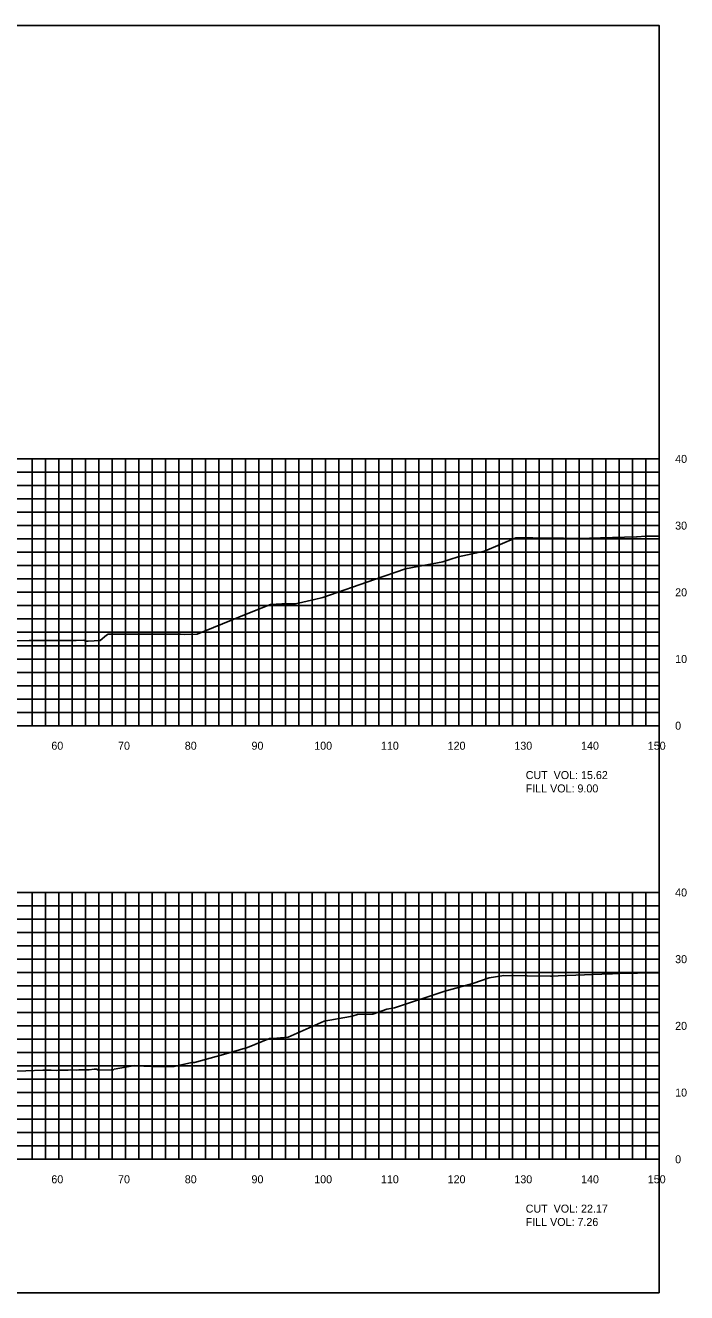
# Model space of a CAD drawing. Extents: x 1797645 to 1803805, y 248417 to 250269.
# Drawn here: x 1802686 to 1802785.1, y 250079.4 to 250269.4 of the extents above; entities that cross this region are included whole.
import ezdxf

# ---------------------------------------------------------------- set-up
doc = ezdxf.new("R2010")
doc.units = 0
for name, color, linetype in [('10', 7, 'Continuous'), ('31', 7, 'Continuous'), ('60', 7, 'Continuous'), ('ANNO-TXT', 7, 'Continuous'), ('Level 62', 7, 'Continuous'), ('M-ROADS', 7, 'Continuous')]:
    doc.layers.add(name, color=color, linetype=linetype)

msp = doc.modelspace()

# ---------------------------------------------------------------- linework, layer by layer
msp.add_lwpolyline([(1802481, 250079.43), (1802781, 250079.43), (1802781, 250269.43), (1802481, 250269.43)], close=True)
at = {"layer": '60'}
for p, q in [((1802781, 250164.43), (1802781, 250204.43)), ((1802781.06, 250204.43), (1802781, 250204.43)), ((1802781.06, 250194.43), (1802781, 250194.43)), ((1802781.06, 250184.43), (1802781, 250184.43)), ((1802781.06, 250174.43), (1802781, 250174.43)), ((1802481, 250164.43), (1802781, 250164.43)), ((1802691, 250164.37), (1802691, 250164.43)), ((1802701, 250164.37), (1802701, 250164.43)), ((1802711, 250164.37), (1802711, 250164.43)), ((1802721, 250164.37), (1802721, 250164.43)), ((1802731, 250164.37), (1802731, 250164.43)), ((1802741, 250164.37), (1802741, 250164.43)), ((1802751, 250164.37), (1802751, 250164.43)), ((1802761, 250164.37), (1802761, 250164.43)), ((1802771, 250164.37), (1802771, 250164.43)), ((1802781, 250164.37), (1802781, 250164.43)), ((1802781.06, 250164.43), (1802781, 250164.43)), ((1802781, 250099.43), (1802781, 250139.43)), ((1802781.06, 250139.43), (1802781, 250139.43)), ((1802781.06, 250129.43), (1802781, 250129.43)), ((1802781.06, 250119.43), (1802781, 250119.43)), ((1802781.06, 250109.43), (1802781, 250109.43)), ((1802481, 250099.43), (1802781, 250099.43)), ((1802691, 250099.37), (1802691, 250099.43)), ((1802701, 250099.37), (1802701, 250099.43)), ((1802711, 250099.37), (1802711, 250099.43)), ((1802721, 250099.37), (1802721, 250099.43)), ((1802731, 250099.37), (1802731, 250099.43)), ((1802741, 250099.37), (1802741, 250099.43)), ((1802751, 250099.37), (1802751, 250099.43)), ((1802761, 250099.37), (1802761, 250099.43)), ((1802771, 250099.37), (1802771, 250099.43)), ((1802781, 250099.37), (1802781, 250099.43)), ((1802781.06, 250099.43), (1802781, 250099.43))]:
    msp.add_line(p, q, dxfattribs=at)
at = {"layer": 'Level 62'}
for p, q in [((1802481, 250204.43), (1802781, 250204.43)), ((1802687, 250164.43), (1802687, 250204.43)), ((1802689, 250164.43), (1802689, 250204.43)), ((1802691, 250164.43), (1802691, 250204.43)), ((1802693, 250164.43), (1802693, 250204.43)), ((1802695, 250164.43), (1802695, 250204.43)), ((1802697, 250164.43), (1802697, 250204.43)), ((1802699, 250164.43), (1802699, 250204.43)), ((1802701, 250164.43), (1802701, 250204.43)), ((1802703, 250164.43), (1802703, 250204.43)), ((1802705, 250164.43), (1802705, 250204.43)), ((1802707, 250164.43), (1802707, 250204.43)), ((1802709, 250164.43), (1802709, 250204.43)), ((1802711, 250164.43), (1802711, 250204.43)), ((1802713, 250164.43), (1802713, 250204.43)), ((1802715, 250164.43), (1802715, 250204.43)), ((1802717, 250164.43), (1802717, 250204.43)), ((1802719, 250164.43), (1802719, 250204.43)), ((1802721, 250164.43), (1802721, 250204.43)), ((1802723, 250164.43), (1802723, 250204.43)), ((1802725, 250164.43), (1802725, 250204.43)), ((1802727, 250164.43), (1802727, 250204.43)), ((1802729, 250164.43), (1802729, 250204.43)), ((1802731, 250164.43), (1802731, 250204.43)), ((1802733, 250164.43), (1802733, 250204.43)), ((1802735, 250164.43), (1802735, 250204.43)), ((1802737, 250164.43), (1802737, 250204.43)), ((1802739, 250164.43), (1802739, 250204.43)), ((1802741, 250164.43), (1802741, 250204.43)), ((1802743, 250164.43), (1802743, 250204.43)), ((1802745, 250164.43), (1802745, 250204.43)), ((1802747, 250164.43), (1802747, 250204.43)), ((1802749, 250164.43), (1802749, 250204.43)), ((1802751, 250164.43), (1802751, 250204.43)), ((1802753, 250164.43), (1802753, 250204.43)), ((1802755, 250164.43), (1802755, 250204.43)), ((1802757, 250164.43), (1802757, 250204.43)), ((1802759, 250164.43), (1802759, 250204.43)), ((1802761, 250164.43), (1802761, 250204.43)), ((1802763, 250164.43), (1802763, 250204.43)), ((1802765, 250164.43), (1802765, 250204.43)), ((1802767, 250164.43), (1802767, 250204.43)), ((1802769, 250164.43), (1802769, 250204.43)), ((1802771, 250164.43), (1802771, 250204.43)), ((1802773, 250164.43), (1802773, 250204.43)), ((1802775, 250164.43), (1802775, 250204.43)), ((1802777, 250164.43), (1802777, 250204.43)), ((1802779, 250164.43), (1802779, 250204.43)), ((1802781, 250164.43), (1802781, 250204.43)), ((1802481, 250202.43), (1802781, 250202.43)), ((1802481, 250200.43), (1802781, 250200.43)), ((1802481, 250198.43), (1802781, 250198.43)), ((1802481, 250196.43), (1802781, 250196.43)), ((1802481, 250194.43), (1802781, 250194.43)), ((1802481, 250192.43), (1802781, 250192.43)), ((1802481, 250190.43), (1802781, 250190.43)), ((1802481, 250188.43), (1802781, 250188.43)), ((1802481, 250186.43), (1802781, 250186.43)), ((1802481, 250184.43), (1802781, 250184.43)), ((1802481, 250182.43), (1802781, 250182.43)), ((1802481, 250180.43), (1802781, 250180.43)), ((1802481, 250178.43), (1802781, 250178.43)), ((1802481, 250176.43), (1802781, 250176.43)), ((1802481, 250174.43), (1802781, 250174.43)), ((1802481, 250172.43), (1802781, 250172.43)), ((1802481, 250170.43), (1802781, 250170.43)), ((1802481, 250168.43), (1802781, 250168.43)), ((1802481, 250166.43), (1802781, 250166.43)), ((1802481, 250164.43), (1802781, 250164.43)), ((1802481, 250139.43), (1802781, 250139.43)), ((1802687, 250099.43), (1802687, 250139.43)), ((1802689, 250099.43), (1802689, 250139.43)), ((1802691, 250099.43), (1802691, 250139.43)), ((1802693, 250099.43), (1802693, 250139.43)), ((1802695, 250099.43), (1802695, 250139.43)), ((1802697, 250099.43), (1802697, 250139.43)), ((1802699, 250099.43), (1802699, 250139.43)), ((1802701, 250099.43), (1802701, 250139.43)), ((1802703, 250099.43), (1802703, 250139.43)), ((1802705, 250099.43), (1802705, 250139.43)), ((1802707, 250099.43), (1802707, 250139.43)), ((1802709, 250099.43), (1802709, 250139.43)), ((1802711, 250099.43), (1802711, 250139.43)), ((1802713, 250099.43), (1802713, 250139.43)), ((1802715, 250099.43), (1802715, 250139.43)), ((1802717, 250099.43), (1802717, 250139.43)), ((1802719, 250099.43), (1802719, 250139.43)), ((1802721, 250099.43), (1802721, 250139.43)), ((1802723, 250099.43), (1802723, 250139.43)), ((1802725, 250099.43), (1802725, 250139.43)), ((1802727, 250099.43), (1802727, 250139.43)), ((1802729, 250099.43), (1802729, 250139.43)), ((1802731, 250099.43), (1802731, 250139.43)), ((1802733, 250099.43), (1802733, 250139.43)), ((1802735, 250099.43), (1802735, 250139.43)), ((1802737, 250099.43), (1802737, 250139.43)), ((1802739, 250099.43), (1802739, 250139.43)), ((1802741, 250099.43), (1802741, 250139.43)), ((1802743, 250099.43), (1802743, 250139.43)), ((1802745, 250099.43), (1802745, 250139.43)), ((1802747, 250099.43), (1802747, 250139.43)), ((1802749, 250099.43), (1802749, 250139.43)), ((1802751, 250099.43), (1802751, 250139.43)), ((1802753, 250099.43), (1802753, 250139.43)), ((1802755, 250099.43), (1802755, 250139.43)), ((1802757, 250099.43), (1802757, 250139.43)), ((1802759, 250099.43), (1802759, 250139.43)), ((1802761, 250099.43), (1802761, 250139.43)), ((1802763, 250099.43), (1802763, 250139.43)), ((1802765, 250099.43), (1802765, 250139.43)), ((1802767, 250099.43), (1802767, 250139.43)), ((1802769, 250099.43), (1802769, 250139.43)), ((1802771, 250099.43), (1802771, 250139.43)), ((1802773, 250099.43), (1802773, 250139.43)), ((1802775, 250099.43), (1802775, 250139.43)), ((1802777, 250099.43), (1802777, 250139.43)), ((1802779, 250099.43), (1802779, 250139.43)), ((1802781, 250099.43), (1802781, 250139.43)), ((1802481, 250137.43), (1802781, 250137.43)), ((1802481, 250135.43), (1802781, 250135.43)), ((1802481, 250133.43), (1802781, 250133.43)), ((1802481, 250131.43), (1802781, 250131.43)), ((1802481, 250129.43), (1802781, 250129.43)), ((1802481, 250127.43), (1802781, 250127.43)), ((1802481, 250125.43), (1802781, 250125.43)), ((1802481, 250123.43), (1802781, 250123.43)), ((1802481, 250121.43), (1802781, 250121.43)), ((1802481, 250119.43), (1802781, 250119.43)), ((1802481, 250117.43), (1802781, 250117.43)), ((1802481, 250115.43), (1802781, 250115.43)), ((1802481, 250113.43), (1802781, 250113.43)), ((1802481, 250111.43), (1802781, 250111.43)), ((1802481, 250109.43), (1802781, 250109.43)), ((1802481, 250107.43), (1802781, 250107.43)), ((1802481, 250105.43), (1802781, 250105.43)), ((1802481, 250103.43), (1802781, 250103.43)), ((1802481, 250101.43), (1802781, 250101.43)), ((1802481, 250099.43), (1802781, 250099.43))]:
    msp.add_line(p, q, dxfattribs=at)
at = {"layer": 'M-ROADS'}
for points in [[(1802680.44, 250177.18), (1802686.56, 250177.19), (1802686.95, 250177.19), (1802687.81, 250177.21), (1802688.3, 250177.19), (1802689.12, 250177.22), (1802689.26, 250177.22), (1802690.37, 250177.23), (1802690.45, 250177.23), (1802691.56, 250177.19), (1802691.77, 250177.2), (1802692.22, 250177.21), (1802692.63, 250177.21), (1802692.81, 250177.21), (1802693.6, 250177.21), (1802694.77, 250177.25), (1802695.09, 250177.12), (1802695.44, 250177.12), (1802697.22, 250177.21), (1802698.15, 250178.02), (1802698.41, 250178.18), (1802698.91, 250178.18), (1802700.64, 250178.18), (1802700.85, 250178.18), (1802700.91, 250178.18), (1802703.14, 250178.18), (1802703.61, 250178.18), (1802708.74, 250178.15), (1802709.27, 250178.14), (1802709.84, 250178.13), (1802711.77, 250178.14), (1802719.35, 250181.26), (1802722.77, 250182.61), (1802724.46, 250182.71), (1802725.48, 250182.71), (1802726.49, 250182.71), (1802729.34, 250183.37), (1802730.61, 250183.67), (1802738.33, 250186.36), (1802742.97, 250187.96), (1802744.85, 250188.3), (1802748.59, 250188.98), (1802749.65, 250189.34), (1802750.87, 250189.74), (1802754.84, 250190.58), (1802759.51, 250192.62), (1802760.92, 250192.62), (1802762.05, 250192.62), (1802766.67, 250192.54), (1802768.92, 250192.52), (1802772.21, 250192.62), (1802777.6, 250192.77), (1802777.65, 250192.77), (1802777.69, 250192.77), (1802777.7, 250192.77), (1802778.95, 250192.83), (1802781, 250192.87)], [(1802680.54, 250112.51), (1802686.08, 250112.69), (1802688.63, 250112.78), (1802689.2, 250112.79), (1802689.89, 250112.81), (1802690.69, 250112.76), (1802691.15, 250112.78), (1802691.69, 250112.8), (1802692.42, 250112.81), (1802692.73, 250112.83), (1802693.66, 250112.79), (1802694.04, 250112.83), (1802694.2, 250112.86), (1802694.39, 250112.84), (1802694.91, 250112.82), (1802695.57, 250112.83), (1802696.33, 250112.94), (1802696.75, 250112.93), (1802696.87, 250112.81), (1802698.88, 250112.83), (1802699.22, 250112.86), (1802699.32, 250112.94), (1802702.41, 250113.47), (1802703.75, 250113.41), (1802704.96, 250113.35), (1802706.51, 250113.35), (1802708.3, 250113.35), (1802708.94, 250113.49), (1802710.97, 250113.94), (1802711.18, 250113.94), (1802711.37, 250113.94), (1802716.05, 250115.26), (1802719.3, 250116.18), (1802722.59, 250117.53), (1802723.08, 250117.56), (1802725.42, 250117.72), (1802730.81, 250120.15), (1802734.73, 250120.85), (1802735.14, 250120.92), (1802735.8, 250121.14), (1802738.09, 250121.2), (1802740.18, 250121.94), (1802741.33, 250122.11), (1802748.86, 250124.63), (1802753.07, 250125.8), (1802755.52, 250126.63), (1802757.74, 250126.96), (1802764.72, 250126.89), (1802765.02, 250126.89), (1802765.87, 250126.92), (1802768.49, 250127.03), (1802773.73, 250127.24), (1802773.99, 250127.25), (1802774.98, 250127.29), (1802780.55, 250127.39), (1802781, 250127.4)]]:
    msp.add_lwpolyline(points, dxfattribs=at)

# ---------------------------------------------------------------- texts
at = {"layer": '10'}
for s, p in [('60', (1802689.9, 250160.83)), ('70', (1802699.9, 250160.83)), ('80', (1802709.9, 250160.83)), ('90', (1802719.9, 250160.83)), ('100', (1802729.3, 250160.83)), ('110', (1802739.3, 250160.83)), ('120', (1802749.3, 250160.83)), ('130', (1802759.3, 250160.83)), ('140', (1802769.3, 250160.83)), ('150', (1802779.3, 250160.83)), ('60', (1802689.9, 250095.83)), ('70', (1802699.9, 250095.83)), ('80', (1802709.9, 250095.83)), ('90', (1802719.9, 250095.83)), ('100', (1802729.3, 250095.83)), ('110', (1802739.3, 250095.83)), ('120', (1802749.3, 250095.83)), ('130', (1802759.3, 250095.83)), ('140', (1802769.3, 250095.83)), ('150', (1802779.3, 250095.83))]:
    msp.add_text(s, height=1.2, dxfattribs=at).set_placement(p)
at = {"layer": '31'}
for s, p in [('40', (1802783.4, 250203.83)), ('30', (1802783.4, 250193.83)), ('20', (1802783.4, 250183.83)), ('10', (1802783.4, 250173.83)), ('0', (1802783.4, 250163.83)), ('40', (1802783.4, 250138.83)), ('30', (1802783.4, 250128.83)), ('20', (1802783.4, 250118.83)), ('10', (1802783.4, 250108.83)), ('0', (1802783.4, 250098.83))]:
    msp.add_text(s, height=1.2, dxfattribs=at).set_placement(p)
at = {"layer": 'ANNO-TXT'}
for s, p in [('CUT  VOL: 15.62', (1802761, 250156.43)), ('FILL VOL: 9.00', (1802761, 250154.43)), ('CUT  VOL: 22.17', (1802761, 250091.43)), ('FILL VOL: 7.26', (1802761, 250089.43))]:
    msp.add_text(s, height=1.2, dxfattribs=at).set_placement(p)

doc.saveas('drawing.dxf')
